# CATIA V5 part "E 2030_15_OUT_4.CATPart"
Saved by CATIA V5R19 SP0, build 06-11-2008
Material "Plastic": density 1200 kg/m3, Young's modulus 2.2e+09 Pa, Poisson ratio 0.38, thermal expansion 6.84e-05 1/K
Bounding box of the stored display mesh (mm): x 60.4 to 75.5, y -7.54 to 7.54, z -2 to 0
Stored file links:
  G:\UTB\Kombinované\Bakalářská práce\Catia\FORMA\E 2030_15_OUT_4.CATPart
  D:\Aplikace\CATIA\Nová složka\win_b64\startup\materials\Catalog.CATMaterial
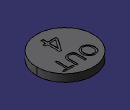
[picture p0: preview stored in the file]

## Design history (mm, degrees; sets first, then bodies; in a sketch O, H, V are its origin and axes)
Body1 "E 2030_15_OUT_1-8" (main body)
  Solid1: solid without history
